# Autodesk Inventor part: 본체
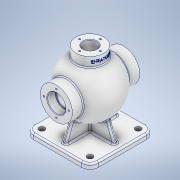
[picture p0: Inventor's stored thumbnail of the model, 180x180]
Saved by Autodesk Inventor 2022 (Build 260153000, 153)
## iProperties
Created: 2024-04
Part Number: 본체
Material: 알루미늄 6061
Document SubType Name: Modeling
Designer: user
Mass: 1526.72 g
Surface Area: 1173.82 cm^2
Volume: 565.453 cm^3
Density: 2.7 g/cm^3
Appearance: 알루미늄 - 평지
Author: user
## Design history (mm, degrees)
sketch "스케치1"
  geometry: L1 (0, 54)-(0, -54); A1 r 54 centre (0, 0) between (0, -54) and (0, 54); 1 further point
  constraints: 2 end point, 2 point on circle, 1 centre point, 1 coincident, 1 midpoint, 1 vertical
  dimensions: "d0" = 108 diameter of A1
revolve "회전1" sketch "스케치1" stored, may be unused: angle "d1" = 90 deg
sketch "스케치2"
  geometry: C1 r 31 at (0, 0); 1 further point
  constraints: 1 centre point, 1 coincident
  dimensions: "d2" = 62 diameter of C1
extrude "돌출1" join sketch "스케치2" stored distance "d3" = 130; taper "d4" = 0 deg
sketch "스케치3"
  geometry: C1 r 27 at (0, 0); 1 further point
  constraints: 1 centre point, 1 coincident
  dimensions: "d5" = 54 diameter of C1
extrude "돌출2" join sketch "스케치3" distance "d6" = 65; taper "d7" = 0 deg
node "작업 평면1"
sketch "스케치4"
  geometry: L1 (62.5, -62.5)-(-62.5, -62.5); L2 (-62.5, -62.5)-(-62.5, 62.5); L3 (-62.5, 62.5)-(62.5, 62.5); L4 (62.5, 62.5)-(62.5, -62.5); L5 (62.5, -62.5)-(-62.5, 62.5); L6 (-62.5, -62.5)-(62.5, 62.5); 1 further point
  constraints: 12 end point, 2 midpoint, 2 parallel, 1 horizontal, 1 perpendicular
  dimensions: "d9" = 125 distance of L1.start L1.end; "d10" = 125 distance of L1.end L2.end
extrude "돌출3" join sketch "스케치4" distance "d11" = 10; taper "d12" = 0 deg
sketch "스케치5"
  geometry: L1 (-75, -62.5)-(-75, 62.5) reference; L2 (-75, 50.5)-(0, 23.202); L3 (0, 23.202)-(0, -23.202); L4 (0, -23.202)-(-75, -50.5); L5 (-115, 0)-(95, 0) reference; L6 (-75, 50.5)-(-75, -50.5); L7 (-85, 62.5)-(-75, 62.5) reference; 1 further point
  constraints: 8 end point, 2 point on line, 1 collinear, 1 midpoint, 1 parallel, 1 other
  dimensions: "d13" = 12 distance from line of L2.start L7; "d14" = 20 deg angle of L7 L2
extrude "돌출4" join sketch "스케치5" stored distance "d15" = 8; taper "d16" = 0 deg
sketch "스케치6"
  geometry: L1 (62.5, -75)-(-62.5, -75) reference; L2 (-50.5, -75)-(-23.202, 0); L3 (-87.5, 0)-(87.5, 0) reference; L4 (-62.5, -85)-(-62.5, -75) reference; 1 further point
  constraints: 2 end point, 2 point on line
  dimensions: "d17" = 20 deg angle of L2 L4; "d18" = 12 distance from line of L2.start L4
feature "리브1" sketch "스케치6" dims "d19" = 1, "d20" = 8, "d21" = 0, "d22" = 0, "d23" = 1, "d24" = 1
sketch "스케치7"
  geometry: L1 (44, 0)-(-44, 0); A1 r 44 centre (0, 0) between (-44, 0) and (44, 0); 1 further point
  constraints: 2 end point, 2 point on circle, 1 centre point, 1 coincident, 1 horizontal, 1 midpoint
  dimensions: "d26" = 44 radius of A1
revolve "회전2" sketch "스케치7" stored, may be unused: angle "d27" = 90 deg
sketch "스케치8"
  geometry: 2 further points
  constraints: 1 coincident
hole "구멍1" sketch "스케치8" at (0, 0) diameter "d28" = 26; stored, may be unused: countersink angle "d32" = 90 deg, drill point angle "d34" = 0 deg; dims "d29" = 8, "d30" = 4, "d31" = 2, "d33" = 10
sketch "스케치9"
  geometry: 2 further points
  constraints: 1 coincident
hole "구멍2" sketch "스케치9" at (0, 0) diameter "d35" = 30; stored, may be unused: countersink angle "d39" = 90 deg, drill point angle "d41" = 0 deg; dims "d36" = 6, "d37" = 35, "d38" = 16, "d40" = 8
fillet "모깎기1" dims "d49" = 16
sketch "스케치10"
  geometry: A1 r 16 centre (46.5, -46.5) between (46.5, -62.5) and (62.5, -46.5) reference; 2 further points
  constraints: 1 coincident
hole "구멍3" sketch "스케치10" at (46.5, -46.5) diameter "d42" = 11; stored, may be unused: countersink angle "d46" = 90 deg, drill point angle "d48" = 0 deg; dims "d43" = 6, "d44" = 35, "d45" = 16, "d47" = 8
sketch "스케치11"
  geometry: L1 (-87.5, 0)-(87.5, 0) reference; 2 further points
  constraints: 1 point on line
  dimensions: "d57" = 20 distance of point (-20, 0) point (0, 0)
hole "구멍4" sketch "스케치11" at (-20, 0) diameter "d50" = 3.242; stored, may be unused: countersink angle "d54" = 90 deg, drill point angle "d56" = 118 deg; dims "d51" = 9, "d52" = 4, "d53" = 2, "d55" = 11
sketch "스케치12"
  geometry: L1 (0, -115)-(0, 95) reference; 2 further points
  constraints: 1 point on line
  dimensions: "d68" = 24 distance of point (0, 24) point (0, 0)
hole "구멍5" sketch "스케치12" at (0, 24) diameter "d61" = 3.242; stored, may be unused: countersink angle "d65" = 90 deg, drill point angle "d67" = 118 deg; dims "d62" = 12, "d63" = 4, "d64" = 2, "d66" = 15
chamfer "모따기1" distance "d72" = 1; stored, may be unused: second distance "d73" = 2, angle "d74" = 45 deg
chamfer "모따기2" distance "d75" = 1; stored, may be unused: second distance "d76" = 2, angle "d77" = 45 deg
chamfer "모따기3" distance "d78" = 1; stored, may be unused: second distance "d79" = 2, angle "d80" = 45 deg
fillet "모깎기2" dims "d81" = 0.6
node "작업 평면2"
sketch "스케치13"
  geometry: L1 (59.002, 20.739)-(59.002, -20.739); L2 (59.002, -20.739)-(52.998, -20.739); L3 (52.998, -20.739)-(52.998, 20.739); L4 (52.998, 20.739)-(59.002, 20.739); L5 (65, -27)-(65, 27) reference; L6 (56, 20.739)-(56, -20.739); L7 (59.002, 0)-(52.998, 0); L8 (-115, 0)-(95, 0) reference; 2 further points
  constraints: 5 midpoint, 4 end point, 1 parallel, 1 point on line, 2 other
  dimensions: "d83" = 9 distance between parallel lines of L5 L6
feature "엠보싱1" sketch "스케치13" dims "d0" = 108, "d9" = 125, "d10" = 125, "d84" = 0.5, "d85" = 0
fillet "모깎기3" dims "d86" = 3
fillet "모깎기4" dims "d87" = 3
node "솔리드1"
mirror "미러1"
mirror "미러2"
mirror "미러3"
mirror "미러4"
pattern_circular "원형 패턴1" dims angle "d59" = 360 deg
pattern_circular "원형 패턴2" dims angle "d70" = 360 deg
mirror "미러5"
feature "A9D066F2-1C7D-4E18-AEED-F7BC21143FA4" dims "d42" = 11, "d43" = 6, "d44" = 35, "d45" = 16, "d46" = 90 deg, "d47" = 8, "d48" = 0
other parameters: "d8" = -85, "d82" = 33.75
